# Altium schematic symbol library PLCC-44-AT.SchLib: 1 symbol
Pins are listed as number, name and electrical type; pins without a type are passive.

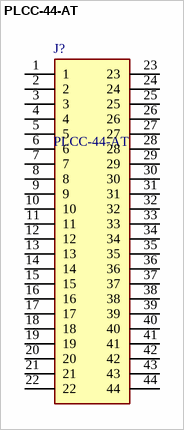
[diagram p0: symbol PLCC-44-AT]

## PLCC-44-AT
designator J?
PLCC 44P THROUGH HOLE; Manufacturer_Name: Adam Tech; Geometry.Height: 8.2mm
footprint PLCC44AT
pins: 1, 2, 3, 4, 5, 6, 7, 8, 9, 10, 11, 12, 13, 14, 15, 16, 17, 18, 19, 20, 21, 22, 23, 24, 25, 26, 27, 28, 29, 30, 31, 32, 33, 34, 35, 36, 37, 38, 39, 40, 41, 42, 43, 44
